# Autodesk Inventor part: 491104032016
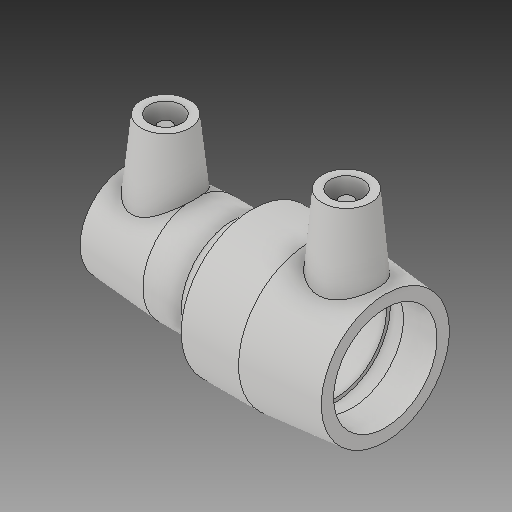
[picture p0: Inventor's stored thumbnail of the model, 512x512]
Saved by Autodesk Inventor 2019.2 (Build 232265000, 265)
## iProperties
Created: 2017-06
Part Number: 491104032016
Material: Generic
Description: PLASSON REDUCING COUPLER 32-16
Document SubType Name: Modeling
Designer: KIM
Mass: 54.8237 g
Surface Area: 155.252 cm^2
Volume: 54.8237 cm^3
Density: 1 g/cm^3
Appearance: Default
Author: KIM
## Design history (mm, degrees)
derived "491104.ipt"
feature "Solid1::491104.ipt"
tag "TaggingFeature1"
body "Solid1"
other parameters: "d2" = 32, "d3" = 35, "d4" = 21, "d5" = 28.8, "d7" = 16, "d8" = 168 deg, "d10" = 14, "d11" = 4.66667, "d14" = 17.6296, "d15" = 35, "d18" = 16, "d19" = 1.75, "d20" = 168 deg, "d22" = 108.92847, "d25" = 135 deg, "d29" = 34, "d30" = 15, "d31" = 28, "d34" = 6 deg, "d35" = 15, "d38" = 25.2, "d39" = 5 deg, "d41" = 4, "d42" = 14, "d43" = 0, "d45" = 4, "d46" = 14, "d47" = 0, "d48" = 32, "d49" = 32, "d50" = 44, "d52" = 14.4, "d53" = 15.6, "d54" = 5.2, "d55" = 168 deg, "d56" = 23.4, "d57" = 39, "d58" = 39.6, "d59" = 1.75, "d60" = 135 deg, "d61" = 42, "d62" = 15, "d64" = 4, "d66" = 5 deg, "d67" = 14, "d68" = 0, "d69" = 28, "d70" = 32, "d71" = 44, "d73" = 41.36, "d76" = 1.75, "d77" = 168 deg, "d78" = 32, "d79" = 1.75, "d80" = 39, "d81" = 14.4, "d82" = 30.08, "d83" = 120 deg, "d88" = 15, "d89" = 24.4, "d90" = 5 deg, "d92" = 4, "d93" = 14, "d94" = 0, "d95" = 3, "d96" = 0, "d97" = 3, "d98" = 0, "d99" = 10.15, "d100" = 2.5375, "d101" = 29.1776, "d102" = 20 deg, "d103" = 11.31, "d104" = 2.8275, "d105" = 40.1192, "d106" = 3.60705, "d107" = 3, "d108" = 0, "d109" = 3, "d110" = 0, "d_1" = 16, "L_2" = 35, "D_1" = 32, "A_1" = 34, "d_2" = 12, "L_1" = 39, "d_" = 32, "A_" = 42, "D_" = 44
